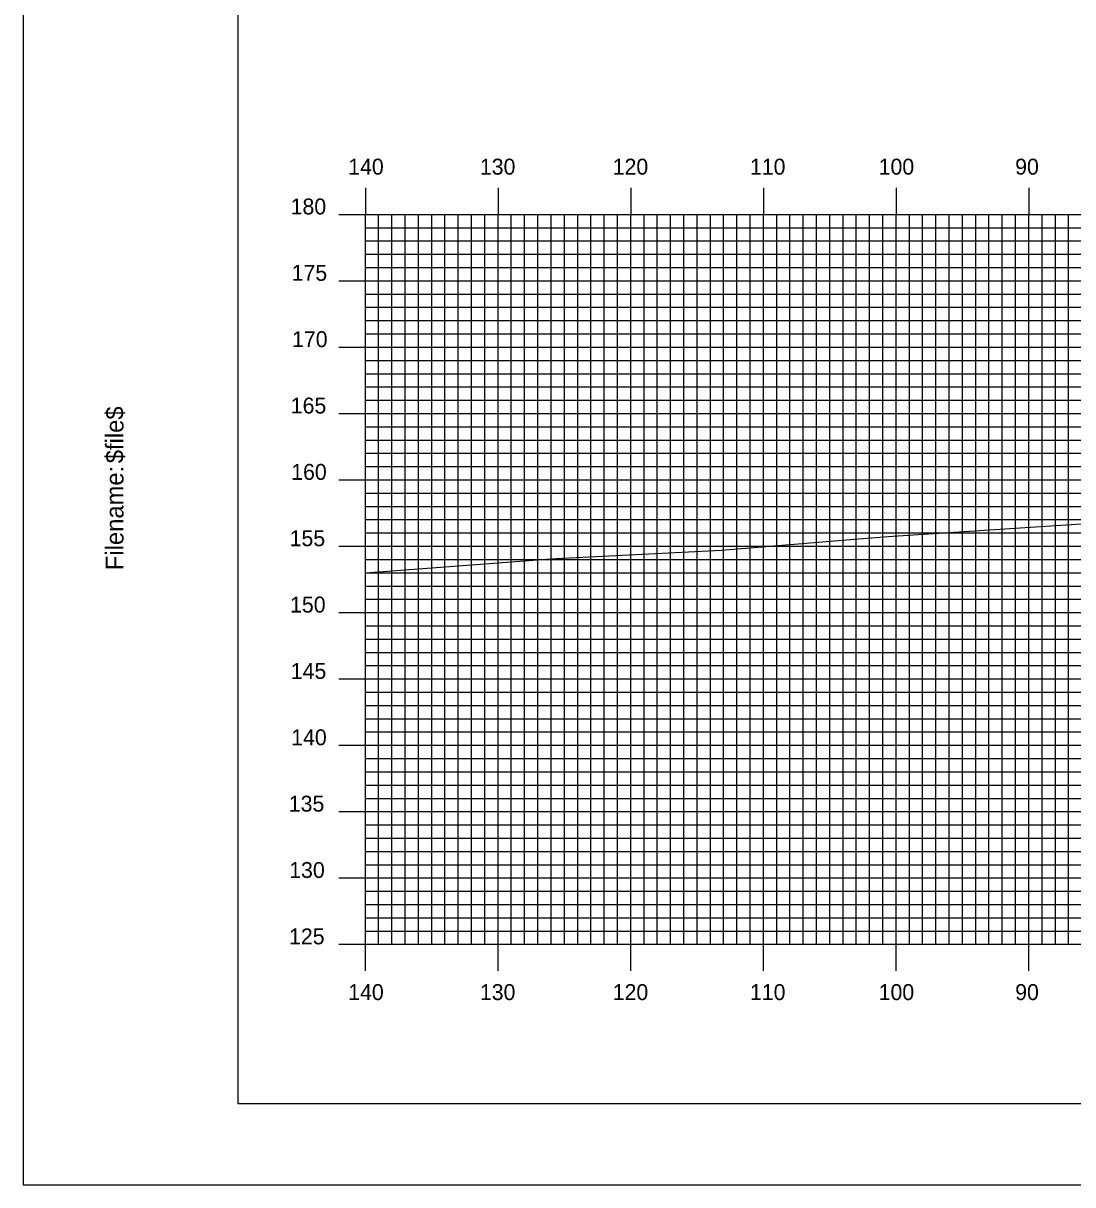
# Model space of a CAD drawing. Extents: x 1783828 to 1784171, y 442591 to 442811.
# Drawn here: x 1783827.7 to 1783906.8, y 442590.5 to 442678.1 of the extents above; entities that cross this region are included whole.
import ezdxf

# ---------------------------------------------------------------- set-up
doc = ezdxf.new("R2010")
doc.units = 0
for name, color, linetype in [('BORDER', 7, 'Continuous'), ('H_V ANNOTATION', 7, 'Continuous'), ('MAJOR', 7, 'Continuous'), ('MINOR', 7, 'Continuous'), ('PLOT BOUNDARY', 7, 'Continuous'), ('S_Roadway_Centerline', 7, 'Continuous')]:
    doc.layers.add(name, color=color, linetype=linetype)

msp = doc.modelspace()

# ---------------------------------------------------------------- linework, layer by layer
at = {"layer": 'BORDER'}
msp.add_lwpolyline([(1783843.886, 442596.665), (1784163.886, 442596.665), (1784163.886, 442806.665), (1783843.886, 442806.665)], close=True, dxfattribs=at)
at = {"layer": 'MAJOR'}
for p, q in [((1783853.486, 442665.669), (1783853.486, 442663.665)), ((1783863.486, 442665.669), (1783863.486, 442663.665)), ((1783873.486, 442665.669), (1783873.486, 442663.665)), ((1783883.486, 442665.669), (1783883.486, 442663.665)), ((1783893.486, 442665.669), (1783893.486, 442663.665)), ((1783903.486, 442665.669), (1783903.486, 442663.665)), ((1783851.482, 442663.665), (1783853.486, 442663.665)), ((1783853.486, 442663.665), (1784133.486, 442663.665)), ((1783853.486, 442608.665), (1783853.486, 442663.665)), ((1783853.486, 442608.665), (1783853.486, 442663.665)), ((1783853.486, 442663.665), (1784133.486, 442663.665)), ((1783863.486, 442608.665), (1783863.486, 442663.665)), ((1783873.486, 442608.665), (1783873.486, 442663.665)), ((1783883.486, 442608.665), (1783883.486, 442663.665)), ((1783893.486, 442608.665), (1783893.486, 442663.665)), ((1783903.486, 442608.665), (1783903.486, 442663.665)), ((1783851.482, 442658.665), (1783853.486, 442658.665)), ((1783853.486, 442658.665), (1784133.486, 442658.665)), ((1783851.482, 442653.665), (1783853.486, 442653.665)), ((1783853.486, 442653.665), (1784133.486, 442653.665)), ((1783851.482, 442648.665), (1783853.486, 442648.665)), ((1783853.486, 442648.665), (1784133.486, 442648.665)), ((1783851.482, 442643.665), (1783853.486, 442643.665)), ((1783853.486, 442643.665), (1784133.486, 442643.665)), ((1783851.482, 442638.665), (1783853.486, 442638.665)), ((1783853.486, 442638.665), (1784133.486, 442638.665)), ((1783851.482, 442633.665), (1783853.486, 442633.665)), ((1783853.486, 442633.665), (1784133.486, 442633.665)), ((1783851.482, 442628.665), (1783853.486, 442628.665)), ((1783853.486, 442628.665), (1784133.486, 442628.665)), ((1783851.482, 442623.665), (1783853.486, 442623.665)), ((1783853.486, 442623.665), (1784133.486, 442623.665)), ((1783851.482, 442618.665), (1783853.486, 442618.665)), ((1783853.486, 442618.665), (1784133.486, 442618.665)), ((1783851.482, 442613.665), (1783853.486, 442613.665)), ((1783853.486, 442613.665), (1784133.486, 442613.665)), ((1783851.482, 442608.665), (1783853.486, 442608.665)), ((1783853.486, 442608.665), (1784133.486, 442608.665)), ((1783853.486, 442608.665), (1784133.486, 442608.665)), ((1783853.486, 442606.661), (1783853.486, 442608.665)), ((1783863.486, 442606.661), (1783863.486, 442608.665)), ((1783873.486, 442606.661), (1783873.486, 442608.665)), ((1783883.486, 442606.661), (1783883.486, 442608.665)), ((1783893.486, 442606.661), (1783893.486, 442608.665)), ((1783903.486, 442606.661), (1783903.486, 442608.665))]:
    msp.add_line(p, q, dxfattribs=at)
at = {"layer": 'MINOR'}
for p, q in [((1783854.486, 442608.665), (1783854.486, 442663.665)), ((1783855.486, 442608.665), (1783855.486, 442663.665)), ((1783856.486, 442608.665), (1783856.486, 442663.665)), ((1783857.486, 442608.665), (1783857.486, 442663.665)), ((1783858.486, 442608.665), (1783858.486, 442663.665)), ((1783859.486, 442608.665), (1783859.486, 442663.665)), ((1783860.486, 442608.665), (1783860.486, 442663.665)), ((1783861.486, 442608.665), (1783861.486, 442663.665)), ((1783862.486, 442608.665), (1783862.486, 442663.665)), ((1783864.486, 442608.665), (1783864.486, 442663.665)), ((1783865.486, 442608.665), (1783865.486, 442663.665)), ((1783866.486, 442608.665), (1783866.486, 442663.665)), ((1783867.486, 442608.665), (1783867.486, 442663.665)), ((1783868.486, 442608.665), (1783868.486, 442663.665)), ((1783869.486, 442608.665), (1783869.486, 442663.665)), ((1783870.486, 442608.665), (1783870.486, 442663.665)), ((1783871.486, 442608.665), (1783871.486, 442663.665)), ((1783872.486, 442608.665), (1783872.486, 442663.665)), ((1783874.486, 442608.665), (1783874.486, 442663.665)), ((1783875.486, 442608.665), (1783875.486, 442663.665)), ((1783876.486, 442608.665), (1783876.486, 442663.665)), ((1783877.486, 442608.665), (1783877.486, 442663.665)), ((1783878.486, 442608.665), (1783878.486, 442663.665)), ((1783879.486, 442608.665), (1783879.486, 442663.665)), ((1783880.486, 442608.665), (1783880.486, 442663.665)), ((1783881.486, 442608.665), (1783881.486, 442663.665)), ((1783882.486, 442608.665), (1783882.486, 442663.665)), ((1783884.486, 442608.665), (1783884.486, 442663.665)), ((1783885.486, 442608.665), (1783885.486, 442663.665)), ((1783886.486, 442608.665), (1783886.486, 442663.665)), ((1783887.486, 442608.665), (1783887.486, 442663.665)), ((1783888.486, 442608.665), (1783888.486, 442663.665)), ((1783889.486, 442608.665), (1783889.486, 442663.665)), ((1783890.486, 442608.665), (1783890.486, 442663.665)), ((1783891.486, 442608.665), (1783891.486, 442663.665)), ((1783892.486, 442608.665), (1783892.486, 442663.665)), ((1783894.486, 442608.665), (1783894.486, 442663.665)), ((1783895.486, 442608.665), (1783895.486, 442663.665)), ((1783896.486, 442608.665), (1783896.486, 442663.665)), ((1783897.486, 442608.665), (1783897.486, 442663.665)), ((1783898.486, 442608.665), (1783898.486, 442663.665)), ((1783899.486, 442608.665), (1783899.486, 442663.665)), ((1783900.486, 442608.665), (1783900.486, 442663.665)), ((1783901.486, 442608.665), (1783901.486, 442663.665)), ((1783902.486, 442608.665), (1783902.486, 442663.665)), ((1783904.486, 442608.665), (1783904.486, 442663.665)), ((1783905.486, 442608.665), (1783905.486, 442663.665)), ((1783906.486, 442608.665), (1783906.486, 442663.665)), ((1783853.486, 442662.665), (1784133.486, 442662.665)), ((1783853.486, 442662.665), (1783855.49, 442662.665)), ((1783853.486, 442661.665), (1784133.486, 442661.665)), ((1783853.486, 442661.665), (1783855.49, 442661.665)), ((1783853.486, 442660.665), (1784133.486, 442660.665)), ((1783853.486, 442660.665), (1783855.49, 442660.665)), ((1783853.486, 442659.665), (1784133.486, 442659.665)), ((1783853.486, 442659.665), (1783855.49, 442659.665)), ((1783853.486, 442657.665), (1784133.486, 442657.665)), ((1783853.486, 442657.665), (1783855.49, 442657.665)), ((1783853.486, 442656.665), (1784133.486, 442656.665)), ((1783853.486, 442656.665), (1783855.49, 442656.665)), ((1783853.486, 442655.665), (1784133.486, 442655.665)), ((1783853.486, 442655.665), (1783855.49, 442655.665)), ((1783853.486, 442654.665), (1784133.486, 442654.665)), ((1783853.486, 442654.665), (1783855.49, 442654.665)), ((1783853.486, 442652.665), (1784133.486, 442652.665)), ((1783853.486, 442652.665), (1783855.49, 442652.665)), ((1783853.486, 442651.665), (1784133.486, 442651.665)), ((1783853.486, 442651.665), (1783855.49, 442651.665)), ((1783853.486, 442650.665), (1784133.486, 442650.665)), ((1783853.486, 442650.665), (1783855.49, 442650.665)), ((1783853.486, 442649.665), (1784133.486, 442649.665)), ((1783853.486, 442649.665), (1783855.49, 442649.665)), ((1783853.486, 442647.665), (1784133.486, 442647.665)), ((1783853.486, 442647.665), (1783855.49, 442647.665)), ((1783853.486, 442646.665), (1784133.486, 442646.665)), ((1783853.486, 442646.665), (1783855.49, 442646.665)), ((1783853.486, 442645.665), (1784133.486, 442645.665)), ((1783853.486, 442645.665), (1783855.49, 442645.665)), ((1783853.486, 442644.665), (1784133.486, 442644.665)), ((1783853.486, 442644.665), (1783855.49, 442644.665)), ((1783853.486, 442642.665), (1784133.486, 442642.665)), ((1783853.486, 442642.665), (1783855.49, 442642.665)), ((1783853.486, 442641.665), (1784133.486, 442641.665)), ((1783853.486, 442641.665), (1783855.49, 442641.665)), ((1783853.486, 442640.665), (1784133.486, 442640.665)), ((1783853.486, 442640.665), (1783855.49, 442640.665)), ((1783853.486, 442639.665), (1784133.486, 442639.665)), ((1783853.486, 442639.665), (1783855.49, 442639.665)), ((1783853.486, 442637.665), (1784133.486, 442637.665)), ((1783853.486, 442637.665), (1783855.49, 442637.665)), ((1783853.486, 442636.665), (1784133.486, 442636.665)), ((1783853.486, 442636.665), (1783855.49, 442636.665)), ((1783853.486, 442635.665), (1784133.486, 442635.665)), ((1783853.486, 442635.665), (1783855.49, 442635.665)), ((1783853.486, 442634.665), (1784133.486, 442634.665)), ((1783853.486, 442634.665), (1783855.49, 442634.665)), ((1783853.486, 442632.665), (1784133.486, 442632.665)), ((1783853.486, 442632.665), (1783855.49, 442632.665)), ((1783853.486, 442631.665), (1784133.486, 442631.665)), ((1783853.486, 442631.665), (1783855.49, 442631.665)), ((1783853.486, 442630.665), (1784133.486, 442630.665)), ((1783853.486, 442630.665), (1783855.49, 442630.665)), ((1783853.486, 442629.665), (1784133.486, 442629.665)), ((1783853.486, 442629.665), (1783855.49, 442629.665)), ((1783853.486, 442627.665), (1784133.486, 442627.665)), ((1783853.486, 442627.665), (1783855.49, 442627.665)), ((1783853.486, 442626.665), (1784133.486, 442626.665)), ((1783853.486, 442626.665), (1783855.49, 442626.665)), ((1783853.486, 442625.665), (1784133.486, 442625.665)), ((1783853.486, 442625.665), (1783855.49, 442625.665)), ((1783853.486, 442624.665), (1784133.486, 442624.665)), ((1783853.486, 442624.665), (1783855.49, 442624.665)), ((1783853.486, 442622.665), (1784133.486, 442622.665)), ((1783853.486, 442622.665), (1783855.49, 442622.665)), ((1783853.486, 442621.665), (1784133.486, 442621.665)), ((1783853.486, 442621.665), (1783855.49, 442621.665)), ((1783853.486, 442620.665), (1784133.486, 442620.665)), ((1783853.486, 442620.665), (1783855.49, 442620.665)), ((1783853.486, 442619.665), (1784133.486, 442619.665)), ((1783853.486, 442619.665), (1783855.49, 442619.665)), ((1783853.486, 442617.665), (1784133.486, 442617.665)), ((1783853.486, 442617.665), (1783855.49, 442617.665)), ((1783853.486, 442616.665), (1784133.486, 442616.665)), ((1783853.486, 442616.665), (1783855.49, 442616.665)), ((1783853.486, 442615.665), (1784133.486, 442615.665)), ((1783853.486, 442615.665), (1783855.49, 442615.665)), ((1783853.486, 442614.665), (1784133.486, 442614.665)), ((1783853.486, 442614.665), (1783855.49, 442614.665)), ((1783853.486, 442612.665), (1784133.486, 442612.665)), ((1783853.486, 442612.665), (1783855.49, 442612.665)), ((1783853.486, 442611.665), (1784133.486, 442611.665)), ((1783853.486, 442611.665), (1783855.49, 442611.665)), ((1783853.486, 442610.665), (1784133.486, 442610.665)), ((1783853.486, 442610.665), (1783855.49, 442610.665)), ((1783853.486, 442609.665), (1784133.486, 442609.665)), ((1783853.486, 442609.665), (1783855.49, 442609.665))]:
    msp.add_line(p, q, dxfattribs=at)
at = {"layer": 'PLOT BOUNDARY'}
msp.add_lwpolyline([(1783827.7, 442590.547), (1784167.7, 442590.547), (1784167.7, 442810.547), (1783827.7, 442810.547)], close=True, dxfattribs=at)
at = {"layer": 'S_Roadway_Centerline'}
msp.add_lwpolyline([(1783853.486, 442636.663), (1783867.466, 442637.714), (1783867.878, 442637.743), (1783868.37, 442637.769), (1783880.327, 442638.354), (1783890.65, 442639.225), (1783893.248, 442639.413), (1783912.063, 442640.656), (1783915.08, 442640.896), (1783918.205, 442641.002), (1783926.751, 442641.42), (1783936.445, 442642.435), (1783949.803, 442643.888), (1783957.509, 442644.418), (1783965.652, 442645.077), (1783980.476, 442646.512), (1783984.4, 442646.921), (1783988.604, 442647.199), (1783997.959, 442647.844), (1784012.537, 442648.67), (1784019.616, 442649.188), (1784025.413, 442649.734)], dxfattribs=at)

# ---------------------------------------------------------------- texts
at = {"layer": 'BORDER'}
for s, p in [('$file$', (1783835.256, 442644.916)), ('$file$', (1783835.256, 442644.916)), ('Filename:', (1783835.256, 442636.862)), ('Filename:', (1783835.256, 442636.862))]:
    msp.add_text(s, height=1.3392, rotation=90, dxfattribs=at).set_placement(p)
at = {"layer": 'H_V ANNOTATION'}
for s, p in [('140', (1783852.191, 442666.665)), ('130', (1783862.116, 442666.665)), ('120', (1783872.127, 442666.665)), ('110', (1783882.47, 442666.665)), ('100', (1783892.17, 442666.665)), ('90', (1783902.459, 442666.665)), ('180', (1783847.853, 442663.665)), ('175', (1783847.928, 442658.665)), ('170', (1783847.96, 442653.665)), ('165', (1783847.864, 442648.665)), ('160', (1783847.896, 442643.665)), ('155', (1783847.778, 442638.665)), ('150', (1783847.81, 442633.665)), ('145', (1783847.864, 442628.665)), ('140', (1783847.896, 442623.665)), ('135', (1783847.714, 442618.665)), ('130', (1783847.746, 442613.665)), ('125', (1783847.735, 442608.665)), ('140', (1783852.191, 442604.465)), ('130', (1783862.116, 442604.465)), ('120', (1783872.127, 442604.465)), ('110', (1783882.47, 442604.465)), ('100', (1783892.17, 442604.465)), ('90', (1783902.459, 442604.465))]:
    msp.add_text(s, height=1.2, dxfattribs=at).set_placement(p)
at = {"layer": 'MAJOR'}
msp.add_text('-', height=0.012, dxfattribs=at).set_placement((1783853.477, 442608.665))

doc.saveas('drawing.dxf')
